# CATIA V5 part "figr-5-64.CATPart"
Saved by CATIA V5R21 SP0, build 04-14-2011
Part number: Part3
Bounding box of the stored display mesh (mm): x -10 to 10, y -10 to 10, z 0 to 26
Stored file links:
  C:\Users\CADCIM\CATIA_v5r21\c15_cat_v5r21\c15-catia-v5r20-prt\Part3.CATPart
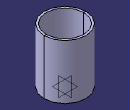
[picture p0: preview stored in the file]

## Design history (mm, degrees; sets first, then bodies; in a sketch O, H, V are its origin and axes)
SheetMetalParameters1: Thickness 1, BendRadius 2, KFactor 0.400515 {= log(min(100,max(20*SheetMetalParameters1.BendRadius,SheetMetalParameters1.Thickness)/SheetMetalParameters1.Thickness))/log(100)/2}, ReliefRadialLength 1, ReliefAxialLength 2, MinimumBendRadius 0
Body1 (main body)
  Sketch1 on xy-plane, origin (0, 0, 0), H (1, 0, 0), V (0, 1, 0)
    circle A1 centre (0, 0) radius 10
    radius A1 = 10
  d_RolledWall1: KFacteur 0.400515 {= SheetMetalParameters1.KFactor}, Extrude_Thickness 1, Extrude_Profile Sketch1, Extrude_StartLength 26, Extrude_EndLength 0, RolledWall_DeductionTable SheetMetalParameters1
